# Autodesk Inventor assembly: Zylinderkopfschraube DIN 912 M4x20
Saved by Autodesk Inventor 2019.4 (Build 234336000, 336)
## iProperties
Created: 2021-06
Part Number: Zylinderkopfschraube DIN 912 M4x20
Document SubType Name: Assembly
Designer: Administrator
Title: Zylinderkopfschraube DIN 912 M4x20 v2
Author: Administrator
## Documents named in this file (2)
- c:\worker\convert-fusion-r04\tmp\job-1\39\output\files\e1e84fd7-b652-4e3d-a1c7-f0a54bbc30a7\Zylinderkopfschraube DIN 912 M4x20 v2_1.iam
- c:\worker\convert-fusion-r04\tmp\job-1\39\output\files\e1e84fd7-b652-4e3d-a1c7-f0a54bbc30a7\HI_WUERTH 00824  20 cylinder head screw DIN 912 M4x20 8.8 BLK.ipt
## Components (1 placed, 1 different names)
1. HI_WUERTH 00824  20 cylinder head screw DIN 912 M4x20 8.8 BLK:1
